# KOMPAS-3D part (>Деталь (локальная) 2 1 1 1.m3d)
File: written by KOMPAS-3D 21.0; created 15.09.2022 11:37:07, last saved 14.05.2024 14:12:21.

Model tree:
1. Эскиз:1

Referenced files in C:\Program Files\Ascon\Libs\EasySteel\: Rolled metal.kle, StandartSolutions.kle, DSTVProperties.lpt
Referenced files in W:\Шаблоны чертежей\: Констр. чертеж А3 гориз. перв. лист.cdt
Referenced files in C:\Program Files\Ascon\Libs\EasySteel\BeltEndings\: 
Referenced files in C:\Program Files\Ascon\Libs\EasySteel\Punctures\: 
Referenced files in C:\Program Files\Ascon\Libs\EasySteel\Insulations\: 
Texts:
  Уголок равнополочный по ГОСТ 8509-93 (Спец)
  config2DpacketName
  config2DstdSizeID
  Констр. чертеж А3 гориз. перв. лист.cdt
  Болт ГОСТ 22353-77
  Шайба ГОСТ 22355-77
  Гайка ГОСТ 22354-77
  Нормальная пружинная шайба ГОСТ 6402-70 (исп. 1)
  SeaRox SL 436
  Сталь 09Г2С ГОСТ 19281-2014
